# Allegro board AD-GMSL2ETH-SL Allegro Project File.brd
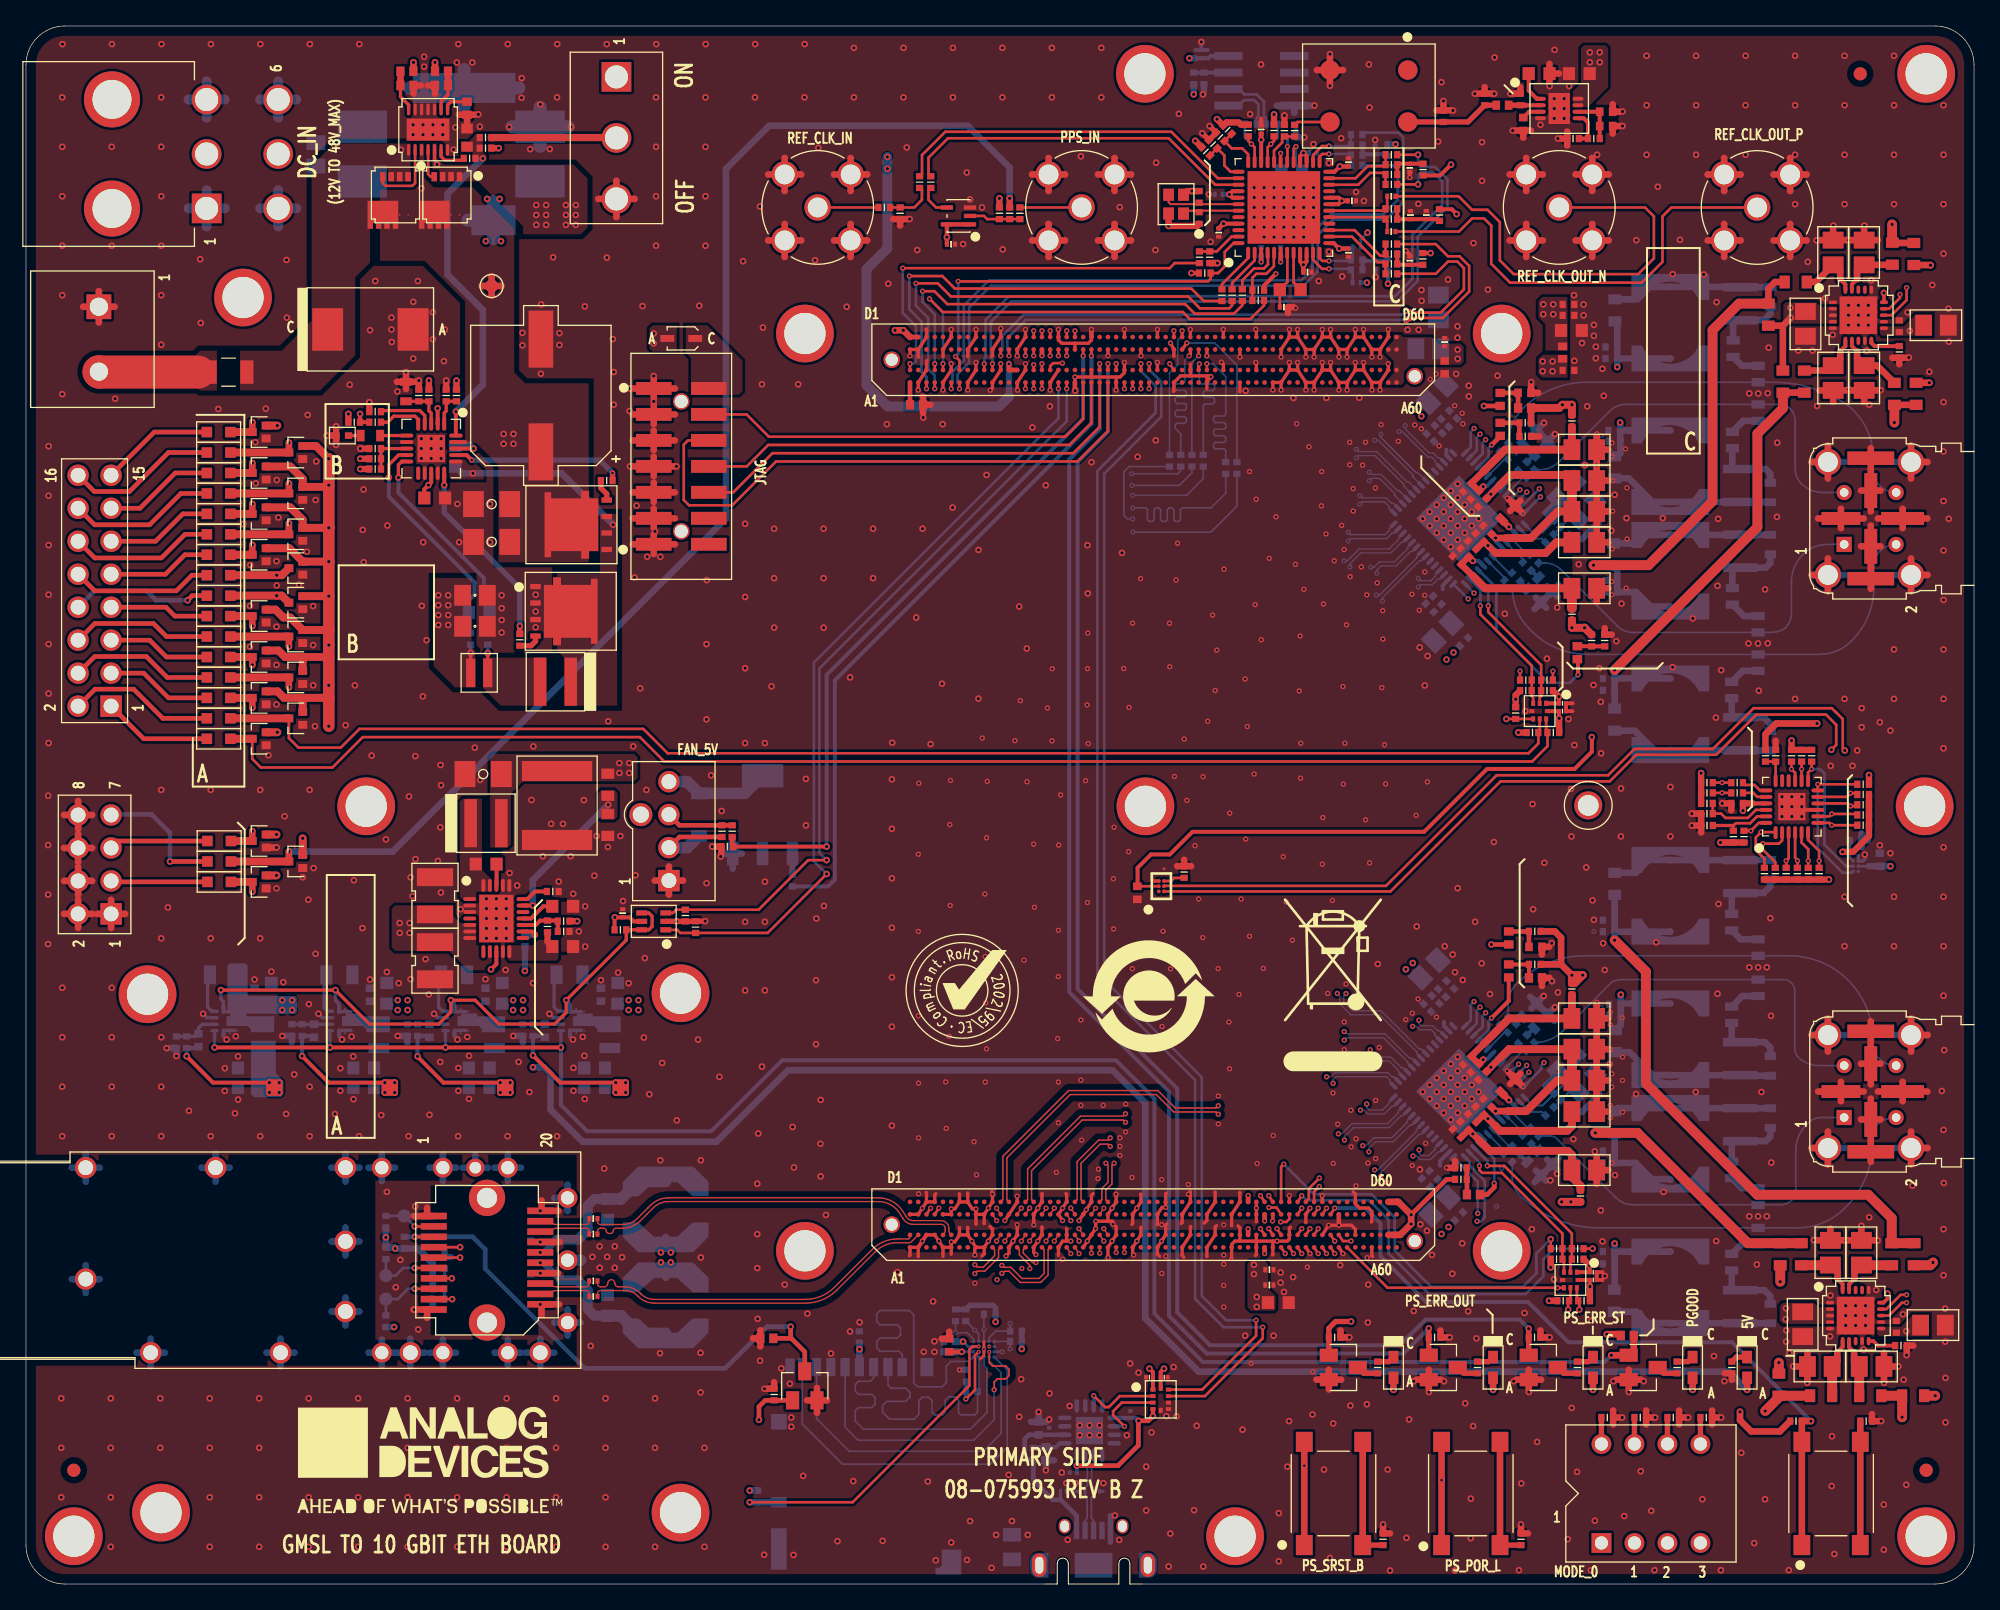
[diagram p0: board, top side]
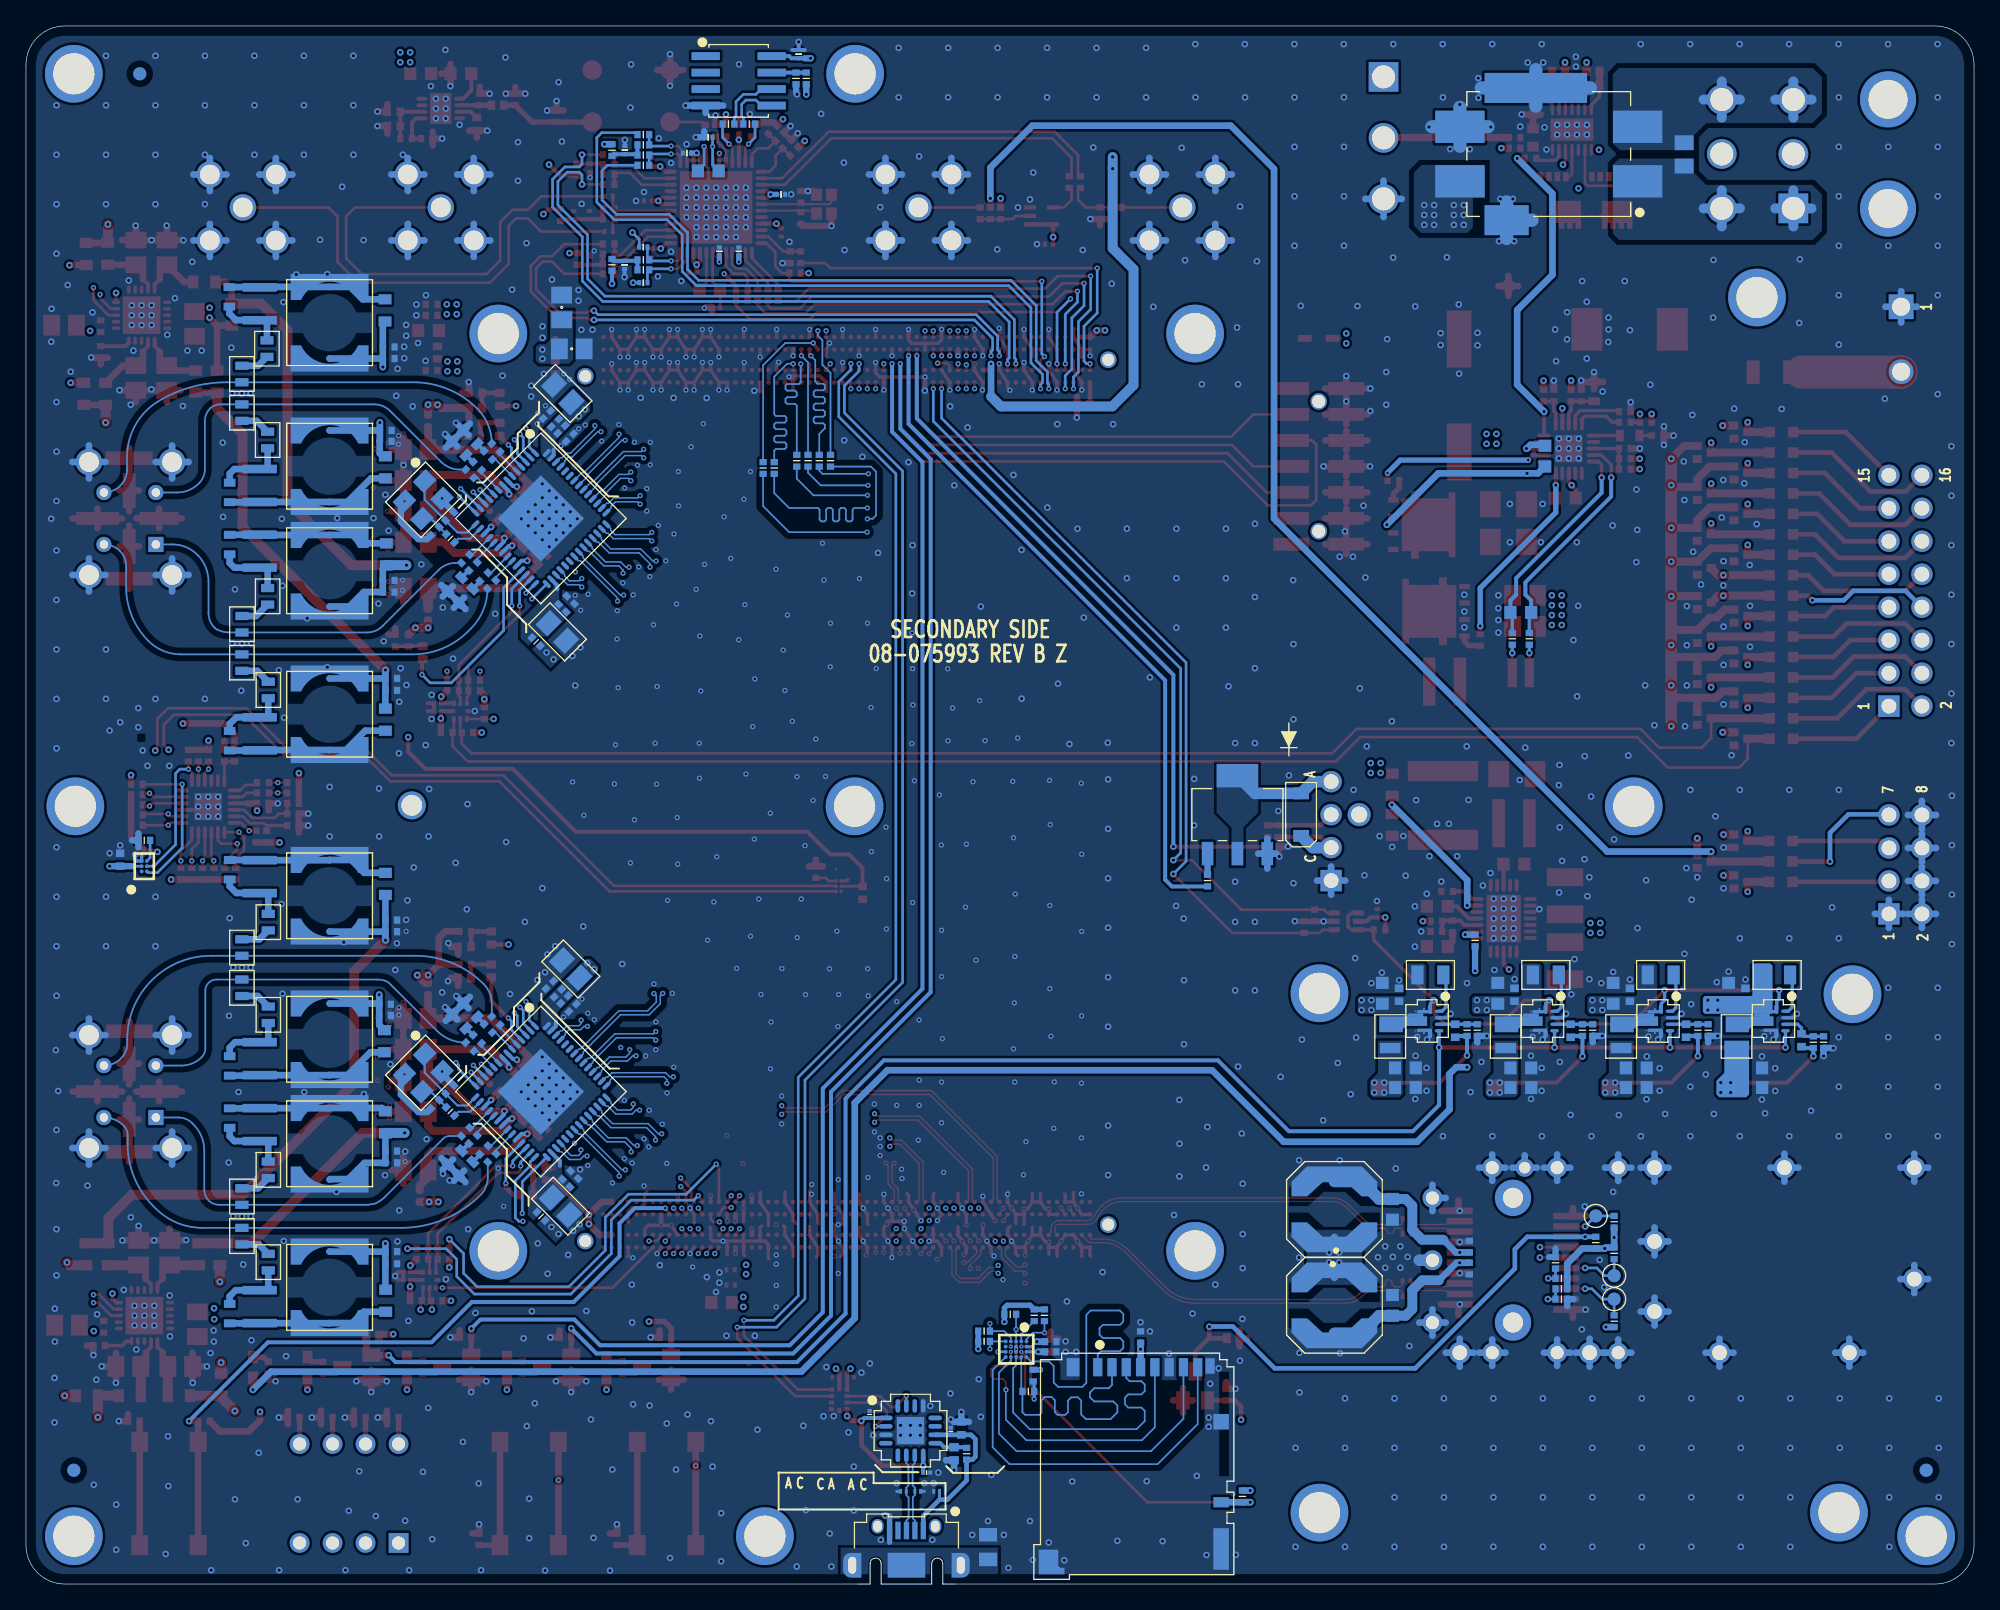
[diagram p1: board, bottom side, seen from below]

Outline 150 x 120 mm; copper layers: TOP, L2_GND, L3_SIG, L4_GND, L5_PWR, L6_PWR, L7_GND, L8_SIG, L9_GND, BOTTOM. Coordinates in mm from the lower left corner of the outline.
Outline path: 0,117 0,3 arc(0.88,0.88) 3,0 79.4,0 79.4,1.58 arc(79.83,2) 80.25,1.58 80.25,0 84.15,0 84.15,1.58 arc(84.58,2) 85,1.58 85,0 147,0 arc(149.12,0.88) 150,3 150,117 arc(149.12,119.12) 147,120 3,120 arc(0.88,119.12) 0,117

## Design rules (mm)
constraint set DEFAULT: min track width 0.203
net group DP_USB: nets USB_DEBUG_N USB_DEBUG_P
net group MG_MIPI1_DP1: nets B_DB3N/DF1N/B3C/F1C B_DB3P/DF1P/B3B/F1B
net group MG_MIPI1_DP2: nets B_DB2N/DF0N/B2B/F0B B_DB2P/DF0P/B2A/F0A
net group MG_MIPI1_DP3: nets B_DB1N/DE1N/B1C/E1C B_DB1P/DE1P/B1B/E1B
net group MG_MIPI1_DP4: nets B_CKBN/CKEN/B1A/E1A B_CKBP/CKEP/B0C/E0C
net group MG_MIPI1_DP5: nets B_DB0N/DE0N/B0B/E0B B_DB0P/DE0P/B0A/E0A
net group MG_MIPI1_DP6: nets B_DA3N/DD1N/A3C/D1C B_DA3P/DD1P/A3B/D1B
net group MG_MIPI1_DP7: nets B_CKAN/CKDN/A3A/D1A B_CKAP/CKDP/A2C/D0C
net group MG_MIPI1_DP8: nets B_DA2N/DD0N/A2B/D0B B_DA2P/DD0P/A2A/D0A
net group MG_MIPI1_DP9: nets B_DA1N/DC1N/A1C/C1C B_DA1P/DC1P/A1B/C1B
net group MG_MIPI1_DP10: nets B_DA0N/DC0N/A0B/C0B B_DA0P/DC0P/A0A/C0A
net group MG_MIPI2_DP1: nets A_DB3N/DF1N/B3C/F1C A_DB3P/DF1P/B3B/F1B
net group MG_MIPI2_DP2: nets A_DB2N/DF0N/B2B/F0B A_DB2P/DF0P/B2A/F0A
net group MG_MIPI2_DP3: nets A_DB1N/DE1N/B1C/E1C A_DB1P/DE1P/B1B/E1B
net group MG_MIPI2_DP4: nets A_CKBN/CKEN/B1A/E1A A_CKBP/CKEP/B0C/E0C
net group MG_MIPI2_DP5: nets A_DB0N/DE0N/B0B/E0B A_DB0P/DE0P/B0A/E0A
net group MG_MIPI2_DP6: nets A_DA3N/DD1N/A3C/D1C A_DA3P/DD1P/A3B/D1B
net group MG_MIPI2_DP7: nets A_CKAN/CKDN/A3A/D1A A_CKAP/CKDP/A2C/D0C
net group MG_MIPI2_DP8: nets A_DA2N/DD0N/A2B/D0B A_DA2P/DD0P/A2A/D0A
net group MG_MIPI2_DP9: nets A_DA1N/DC1N/A1C/C1C A_DA1P/DC1P/A1B/C1B
net group MG_MIPI2_DP10: nets A_DA0N/DC0N/A0B/C0B A_DA0P/DC0P/A0A/C0A
net group SFP_DP1_1: nets UNNAMED_11_CAP_I31_N2 UNNAMED_11_CAP_I32_N2
net group SFP_DP2: nets UNNAMED_11_CAP_I29_N2 UNNAMED_11_CAP_I30_N2
net group SFP_RX_MG: nets SFP+_RX_N SFP+_RX_P
net group SFP_TX_MG: nets SFP+_TX_N SFP+_TX_P
net group SD_CARD_MG: nets SDIO_CLK SDIO_CMD SDIO_DAT0 SDIO_DAT1 SDIO_DAT2 SDIO_DAT3
net group SDCARD_0: nets UNNAMED_6_CN240PABCD_I2_N36 UNNAMED_6_CN240PABCD_I2_N37 UNNAMED_6_CN240PABCD_I3_N34 UNNAMED_6_CN240PABCD_I3_N35 UNNAMED_6_CN240PABCD_I3_N36 UNNAMED_6_CN240PABCD_I4_N34
net group SDCARD_1: nets PS_MIO46_501_SDIO_DAT0 PS_MIO47_501_SDIO_DAT1 PS_MIO48_501_SDIO_DAT2 PS_MIO49_501_SDIO_DAT3 PS_MIO50_501_SDIO_CMD PS_MIO51_501_SDIO_CLK

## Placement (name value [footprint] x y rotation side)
C1  22uF  [C0603]  44.78 28.85 270 bottom
C2  0.1uF  [C0402]  38.86 24.29 270 bottom
C3  0.1uF  [C0402]  38.86 25.99 90 bottom
C4  10uF  [C0805H53]  119.99 87.37 0 top
C5  0.1uF  [C0402]  110.97 84.45 225 top
C6  0.01UF  [C0402]  111.56 83.86 225 top
C7  10uF  [C0805H53]  119.99 84.99 0 top
C8  10uF  [C0805H53]  108.66 91.69 45 bottom
C9  0.1uF  [C0402]  112.52 81.2 135 top
C10  27pF  [C0402]  117.37 82.22 135 bottom
C11  0.1uF  [C0402]  108.74 88.32 225 bottom
C12  0.1uF  [C0402]  109.28 90.04 45 bottom
C13  0.01UF  [C0402]  109.87 89.45 45 bottom
C14  0.01UF  [C0402]  108.15 88.91 225 bottom
C15  10uF  [C0805H53]  119.99 82.61 0 top
C16  0.1uF  [C0402]  112.14 83.28 225 top
C17  22pF  [C0402]  118.5 81.09 315 bottom
C18  0.1uF  [C0402]  111.94 80.61 135 top
C19  0.01UF  [C0402]  111.35 80.03 135 top
C20  0.01UF  [C0402]  110.77 79.44 135 top
C21  0.1uF  [C0402]  110.19 78.86 135 top
C22  10uF  [C0805H53]  119.99 76.69 0 top
C23  0.01UF  [C0402]  108.67 75.77 135 bottom
C24  0.1uF  [C0402]  108.09 75.18 135 bottom
C25  10uF  [C0805H53]  109.08 73.33 225 bottom
C26  10uF  [C0805H53]  137.02 97.05 270 top
C27  10uF  [C0805H53]  139.15 102.55 90 top
C28  10uF  [C0805H53]  139.15 92.89 270 top
C29  10uF  [C0805H53]  141.54 92.89 270 top
C30  10uF  [C0805H53]  141.54 102.55 90 top
C31  0.1uF  [C0402]  144.25 96.88 90 top
C32  10uF  [C0805H53]  147.07 96.95 0 top
C33  0.1uF  [C0402]  121.87 68.83 180 bottom
C34  0.1uF  [C0402]  122.07 76.4 180 bottom
C35  0.1uF  [C0402]  122.3 88.85 180 bottom
C36  0.1uF  [C0402]  122.07 95.28 180 bottom
C37  0.01UF  [C0402]  121.87 69.75 180 bottom
C38  0.01UF  [C0402]  122.07 77.29 180 bottom
C39  0.01UF  [C0402]  122.3 88.01 180 bottom
C40  0.01UF  [C0402]  122.07 94.39 180 bottom
C41  0.22UF  [C0402]  114.73 77.56 315 bottom
C42  0.22UF  [C0402]  115.57 78.38 315 bottom
C43  0.22UF  [C0402]  115.24 86.1 45 bottom
C44  0.22UF  [C0402]  114.4 86.94 45 bottom
C45  0.22UF  [C0402]  114.15 76.98 135 bottom
C46  0.22UF  [C0402]  116.15 78.96 135 bottom
C47  0.22UF  [C0402]  115.82 85.51 225 bottom
C48  0.22UF  [C0402]  113.82 87.52 225 bottom
C49  0.1uF  [C0402]  122.35 44.65 180 bottom
C50  0.1uF  [C0402]  121.87 51.13 180 bottom
C51  0.1uF  [C0402]  121.87 24.66 180 bottom
C52  0.1uF  [C0402]  121.87 33.35 180 bottom
C53  0.01UF  [C0402]  122.35 43.79 180 bottom
C54  0.01UF  [C0402]  121.87 50.24 180 bottom
C55  0.01UF  [C0402]  121.87 25.6 180 bottom
C56  0.01UF  [C0402]  121.87 32.44 180 bottom
C57  0.22UF  [C0402]  114.73 33.43 315 bottom
C58  0.22UF  [C0402]  115.57 34.24 315 bottom
C59  0.22UF  [C0402]  115.24 41.96 45 bottom
C60  0.22UF  [C0402]  114.4 42.8 45 bottom
C61  0.22UF  [C0402]  115.82 41.38 225 bottom
C62  0.22UF  [C0402]  113.82 43.38 225 bottom
C63  0.22UF  [C0402]  114.12 32.82 135 bottom
C64  0.22UF  [C0402]  116.15 34.82 135 bottom
C65  10uF  [C0805H53]  119.99 43.56 0 top
C66  0.1uF  [C0402]  110.97 40.31 225 top
C67  0.01UF  [C0402]  111.56 39.73 225 top
C68  10uF  [C0805H53]  119.99 41.19 0 top
C69  0.1uF  [C0402]  112.14 39.14 225 top
C70  10uF  [C0805H53]  108.05 47.37 45 bottom
C71  27pF  [C0402]  117.37 38.09 135 bottom
C72  0.1uF  [C0402]  108.51 44.4 225 bottom
C73  0.1uF  [C0402]  109.06 46.13 45 bottom
C74  0.01UF  [C0402]  107.93 45 225 bottom
C75  0.01UF  [C0402]  109.64 45.53 45 bottom
C76  10uF  [C0805H53]  119.99 38.79 0 top
C77  0.1uF  [C0402]  112.52 37.06 135 top
C78  22pF  [C0402]  118.5 36.95 315 bottom
C79  0.1uF  [C0402]  111.94 36.47 135 top
C80  0.01UF  [C0402]  111.35 35.89 135 top
C81  0.01UF  [C0402]  110.77 35.31 135 top
C82  0.1uF  [C0402]  110.19 34.72 135 top
C83  10uF  [C0805H53]  119.99 31.88 0 top
C84  0.01UF  [C0402]  108.38 31.5 135 bottom
C85  0.1uF  [C0402]  107.8 30.91 135 bottom
C86  10uF  [C0805H53]  108.84 29.11 225 bottom
C87  10uF  [C0805H53]  136.81 20.01 270 top
C88  10uF  [C0805H53]  138.94 25.52 90 top
C89  10uF  [C0805H53]  138.13 16.76 180 top
C90  10uF  [C0805H53]  142.11 16.76 0 top
C91  10uF  [C0805H53]  141.33 25.52 90 top
C92  0.1uF  [C0402]  144.02 19.81 90 top
C93  10uF  [C0805H53]  146.84 19.94 0 top
C94  0.1uF  [C0201]  99.11 110.21 0 bottom
C95  0.1uF  [C0201]  101.83 102.54 270 top
C96  0.22uF  [C0201]  96.86 98.35 0 top
C97  0.1uF  [C0201]  102.09 106.53 0 top
C98  0.1uF  [C0201]  71.23 103.19 0 top
C99  0.1uF  [C0201]  98.68 101.04 0 top
C100  3900pF  [C0603]  97.34 99.7 0 top
C101  0.1uF  [C0201]  91.85 104.09 270 top
C102  0.1uF  [C0201]  101.83 109.5 90 top
C103  1uF  [C0402]  118.77 98.55 0 top
C104  1uF  [C0402]  118.77 97.71 0 top
C105  10uF  [C0603]  119 96.55 0 top
C106  1uF  [C0402]  118.77 93.47 0 top
C107  15pF  [C0402]  90.33 105.21 270 top
C108  15pF  [C0402]  90.33 106.84 270 top
C109  1uF  [C0402]  115.06 114.34 90 top
C110  0.1uF  [C0201]  95.11 102.64 90 bottom
C111  0.1uF  [C0201]  95.11 112.03 90 top
C112  1uF  [C0402]  112.32 114.34 90 top
C113  3900pF  [C0603]  97.46 108.84 180 bottom
C114  0.1uF  [C0201]  118.31 67.83 0 top
C115  0.1uF  [C0201]  118.31 67.23 0 top
C116  0.22uF  [C0201]  97.46 111.43 0 bottom
C117  0.1uF  [C0402]  109.14 113.05 90 top
C118  10uF  [C0603]  116.51 116.33 0 top
C119  0.1uF  [C0201]  90.5 117.83 90 bottom
C120  0.1uF  [C0201]  103.89 110.44 270 bottom
C121  0.1uF  [C0201]  43.69 23.34 180 top
C122  0.1uF  [C0201]  103.91 101.6 90 bottom
C123  0.1uF  [C0201]  120.68 24.02 0 top
C124  0.1uF  [C0201]  120.68 23.42 0 top
C125  0.1uF  [C0201]  43.69 28.14 180 top
C126  0.1uF  [C0201]  43.69 22.15 180 top
C127  0.1uF  [C0201]  102.46 100.23 0 bottom
C128  0.1uF  [C0201]  102.46 102.97 0 bottom
C129  10uF  [C0603]  18.89 45.5 90 bottom
C130  10uF  [C0603]  45.56 45.5 90 bottom
C131  10uF  [C0603]  27.78 45.5 90 bottom
C132  1uF  [C0402]  17.6 45.39 90 bottom
C133  1uF  [C0402]  44.27 45.39 90 bottom
C134  1uF  [C0402]  26.49 45.39 90 bottom
C135  10pF  [C0402]  22.17 42.61 90 bottom
C136  22uF  [C0603]  17.12 38.24 180 bottom
C137  22uF  [C0603]  43.79 39.75 180 bottom
C138  22uF  [C0603]  26.01 39.75 180 bottom
C139  22uF  [C0603]  17.12 39.75 180 bottom
C140  22uF  [C0603]  43.79 38.24 180 bottom
C141  22uF  [C0603]  26.01 38.24 180 bottom
C142  0.1uF  [C0201]  43.69 26.95 180 top
C143  0.1uF  [C0402]  142.75 55.79 90 bottom
C144  0.1uF  [C0402]  85.57 53.24 270 top
C145  10pF  [C0402]  39.95 42.61 90 bottom
C146  10pF  [C0402]  31.06 42.61 90 bottom
C147  10pF  [C0402]  13.28 41.88 90 bottom
C148  0.1uF  [C0201]  106.55 101.92 270 top
C149  0.1uF  [C0201]  105.13 104.17 0 top
C150  0.1uF  [C0201]  105.13 106.88 0 top
C151  0.1uF  [C0201]  106.55 109.07 90 top
C152  10uF  [C0805H53]  119.99 80.23 0 top
C153  0.1uF  [C0402]  115.39 91.74 0 top
C154  10uF  [C0805H53]  119.99 36.39 0 top
C155  0.1uF  [C0402]  116.23 49.07 0 top
C156  1uF  [C0402]  71.09 18.39 90 top
C157  0.1uF  [C0201]  91.86 107.03 180 bottom
C158  0.1uF  [C0201]  96.61 102.64 90 bottom
C159  47uF  [C0805H60]  107.98 95.14 180 bottom
C160  47uF  [C0805H60]  108.76 98.32 90 bottom
C161  1uF  [C0402]  109.24 93.7 270 top
C162  0.1uF  [C0201]  109.24 95.65 90 top
C163  22uF  [C0603]  96.43 21.68 0 top
C164  0.1uF  [C0201]  95.75 24.21 0 top
C165  0.1uF  [C0201]  95.75 23.03 0 top
C222  47UF  [CPLSMSQ406H488]  39.65 91.54 90 top
C223  2.2uF  [C1206H71]  35.85 80.26 180 top
C224  2.2uF  [C1206H71]  35.85 83.17 180 top
C225  1uF  [C0402]  115.29 112.45 270 top
C226  10uF  [C0603]  119.61 116.33 180 top
C227  1000pF  [C0402H22]  24.36 88.45 180 top
C228  2.2uF  [C0603]  31.47 83.64 0 top
C229  0.1UF  [C0603]  33.05 86.87 270 bottom
C230  22NF  [C0603]  34.9 74.83 180 bottom
C231  47uF  [C0805H60]  34.57 73.76 0 top
C232  47uF  [C0805H60]  34.57 76.15 0 top
C233  0.1uF  [C0402]  121.68 113.39 0 top
C234  1uF  [C0402]  121.68 112.29 0 top
C235  0.1uF  [C0402]  131.76 60.12 180 top
C240  1UF  [C0805]  22.33 110.11 90 bottom
C245  4.7UF  [C1210H110]  31.5 53.01 90 top
C246  4.7UF  [C1210H110]  31.5 48.01 270 top
C247  0.1UF  [C0603]  35.43 55.45 0 top
C248  5600pF  [C0603]  41.33 52.2 0 top
C249  2.2uF  [C0603]  41.33 49.1 0 top
C250  10uF  [C0603]  36.67 45.5 90 bottom
C251  22uF  [C1206H71]  35.2 62.38 180 top
C252  47UF  [C2220H98]  40.89 59.96 270 top
C253  4.7uF  [C0402]  72.44 16.05 90 bottom
C254  22uF  [C0603]  44.78 21.46 90 bottom
C255  0.1uF  [C0402#2]  71.09 18.67 180 bottom
C256  0.1uF  [C0402#2]  71.09 17.88 180 bottom
C257  0.1uF  [C0402#2]  64.18 19.02 90 bottom
C258  0.1uF  [C0201]  85.04 13.06 90 bottom
C259  0.1uF  [C0201]  78.79 11.76 90 bottom
C260  2.2uF  [C0402]  77.98 11.99 90 bottom
C261  0.1uF  [C0201]  80.65 8.59 180 bottom
C262  0.1uF  [C0201]  86.51 15.93 180 top
C263  0.1uF  [C0201]  87.65 15.93 0 top
C267  0.1uF  [C0201]  107.82 105.44 270 top
C268  0.1uF  [C0201]  106.6 105.44 270 top
C271  0.1uF  [C0201]  45.95 51.66 90 top
C272  1000pF  [C0603#2]  33.96 111.4 90 top
C273  1uF  [C0402]  35.38 45.39 90 bottom
C274  22uF  [C0603]  34.9 38.24 180 bottom
C275  22uF  [C0603]  34.9 39.75 180 bottom
D1  MMSD4148T1G  [SOD123-2]  51.82 59.26 90 bottom
D2  SESD0201X1UN-0020-09  [D0201]  79.88 7.14 0 bottom
D3  BAT54JFILM  [SOD323-6]  50.46 95.94 180 top
D4  SESD0201X1UN-0020-09  [D0201]  81.33 7.14 180 bottom
D5  SESD0201X1UN-0020-09  [D0201]  82.43 7.14 0 bottom
D6  RB558WMTL  [SOT416]  20.78 55.65 90 top
D7  RB558WMTL  [SOT416]  17.96 71.4 90 top
D8  RB558WMTL  [SOT416]  17.96 74.55 90 top
D9  RB558WMTL  [SOT416]  17.96 79.27 90 top
D10  RB558WMTL  [SOT416]  17.96 82.42 90 top
D11  RB558WMTL  [SOT416]  17.96 85.57 90 top
D12  RB558WMTL  [SOT416]  17.96 88.72 90 top
D13  SMCJ48A  [DO214AB-4]  26.52 96.63 0 top
D14  RB558WMTL  [SOT416]  20.78 72.97 90 top
D15  RB558WMTL  [SOT416]  20.78 75.58 90 top
D16  RB558WMTL  [SOT416]  20.78 78.24 90 top
D17  RB558WMTL  [SOT416]  20.78 80.85 90 top
D18  RB558WMTL  [SOT416]  20.78 84 90 top
D19  RB558WMTL  [SOT416]  20.78 87.15 90 top
D20  RB558WMTL  [SOT416]  17.96 65.1 90 top
D21  RB558WMTL  [SOT416]  20.78 66.67 90 top
D22  RB558WMTL  [SOT416]  17.96 68.25 90 top
D23  RB558WMTL  [SOT416]  17.96 54.08 90 top
D24  RB558WMTL  [SOT416]  20.78 69.82 90 top
D25  RB558WMTL  [SOT416]  17.96 57.23 90 top
DS6  APT1608SURCK  [LED0603]  105.3 16.68 270 top
DS8  APT1608SURCK  [LED0603]  112.97 16.68 270 top
DS9  APT1608SURCK  [LED0603]  120.66 16.68 270 top
DS10  APT1608SURCK  [LED0603]  128.33 16.68 270 top
DS11  APT1608SURCK  [LED0603]  132.53 16.68 270 top
E1  120OHM  [L0402]  118.32 94.84 270 top
E2  120OHM  [L0402]  113.69 113.89 180 top
F1  10A  [F1206H60]  15.6 93.34 0 top
FL1  BNX026H01L  [FLSML476W358H146]  32.74 110.13 0 bottom
J1  142-0701-201  [CNJOHNSON142-0701-201]  81.28 106.02 0 top
J2  142-0701-201  [CNJOHNSON142-0701-201]  60.96 106.02 0 top
J3  142-0701-201  [CNJOHNSON142-0701-201]  133.3 106.02 0 top
J4  142-0701-201  [CNJOHNSON142-0701-201]  118.06 106.02 0 top
L1  22UH  [LSMSQ240H126]  126.62 66.99 270 bottom
L2  22UH  [LSMSQ240H126]  126.62 78.04 90 bottom
L3  22UH  [LSMSQ240H126]  126.62 86.09 270 bottom
L4  22UH  [LSMSQ240H126]  126.62 97.15 90 bottom
L5  6.8UH  [L1210H118]  132 65.48 90 bottom
L6  6.8UH  [L1210H118]  132 79.55 270 bottom
L7  6.8UH  [L1210H118]  132 84.61 90 bottom
L8  6.8UH  [L1210H118]  132 98.6 270 bottom
L9  0.47UH  [L7144]  131.34 68.86 90 bottom
L10  4.7uH  [LSMSQ236H98]  49.25 21.46 270 bottom
L11  4.7uH  [LSMSQ236H98]  49.25 28.85 90 bottom
L12  0.47UH  [L7144]  131.39 76.07 270 bottom
L13  0.47UH  [L7144]  131.39 88.11 90 bottom
L14  0.47UH  [L7144]  131.44 95.15 270 bottom
L15  22UH  [LSMSQ240H126]  126.62 41.96 270 bottom
L16  22UH  [LSMSQ240H126]  126.62 53.01 90 bottom
L17  22UH  [LSMSQ240H126]  126.62 22.85 270 bottom
L18  22UH  [LSMSQ240H126]  126.62 33.91 90 bottom
L19  6.8UH  [L1210H118]  132 40.46 90 bottom
L20  6.8UH  [L1210H118]  132 54.48 270 bottom
L21  6.8UH  [L1210H118]  132 21.36 90 bottom
L22  6.8UH  [L1210H118]  132 35.38 270 bottom
L23  0.47UH  [L7144]  131.34 43.84 90 bottom
L24  0.47UH  [L7144]  131.34 50.98 270 bottom
L25  0.47UH  [L7144]  131.34 24.79 90 bottom
L26  0.47UH  [L7144]  131.34 31.9 270 bottom
L27  0.33UH  [L0806H39]  18.28 42.17 270 bottom
L28  0.33UH  [L0806H39]  44.95 42.17 270 bottom
L29  0.33UH  [L0806H39]  27.17 42.17 270 bottom
L30  0.47UH  [L7144]  133.38 70.97 90 bottom
L31  1.2UH  [LSMSQ157H122]  40.77 69.49 180 top
L32  0.33UH  [L0806H39]  36.06 42.17 270 bottom
L33  6.8uH  [LSMSQ157H122]  35.42 58.6 0 top
L34  0.47UH  [L7144]  133.37 73.92 270 bottom
L35  0.47UH  [L7144]  133.38 90.22 90 bottom
L36  0.47UH  [L7144]  133.38 93.19 270 bottom
L37  0.47UH  [L7144]  133.38 49.02 270 bottom
L38  0.47UH  [L7144]  133.38 26.8 90 bottom
L39  0.47UH  [L7144]  133.38 29.84 270 bottom
L40  0.47UH  [L7144]  133.38 45.92 90 bottom
M4  2007194-1  [MTE2007194-1]  35.5 24.94 270 top
NOREF  -  []  61.8 229.29 0 top
NOREF#2  -  []  -218.17 164.47 0 top
NOREF#3  -  []  -218.22 187.32 0 top
NOREF#4  -  []  3.68 3.68 0 top
NOREF#5  -  [unnamed#2]  50.4 45.5 270 top
NOREF#6  -  []  148.06 119.81 0 top
NOREF#7  -  [unnamed#2]  3.68 3.68 270 top
NOREF#8  -  []  72.82 231.57 0 top
NOREF#9  -  []  150 39.09 0 top
NOREF#10  -  []  -67.21 -246.71 0 top
NOREF#11  -  []  84.66 7.14 0 top
NOREF#12  -  [unnamed#2]  146.32 116.32 270 top
NOREF#13  -  []  3.68 3.68 0 top
NOREF#14  -  []  82.2 0 0 top
NOREF#15  -  [unnamed#2]  113.63 25.66 270 top
NOREF#16  -  [unnamed#2]  50.4 5.5 270 top
NOREF#17  -  []  70.46 199.62 90 top
NOREF#18  -  []  40.84 111.14 270 top
NOREF#19  -  [unnamed#2]  16.71 99.09 270 top
NOREF#20  -  []  61.8 188.73 0 top
NOREF#21  -  []  86.46 45.26 0 top
NOREF#22  -  [unnamed#2]  113.63 96.31 270 top
NOREF#23  -  [unnamed#2]  59.98 96.31 270 top
NOREF#24  -  []  63.18 173.35 270 top
NOREF#25  -  []  78.87 229.26 90 top
NOREF#26  -  [unnamed#2]  86.2 59.9 270 top
NOREF#27  -  [unnamed#2]  3.68 8.76 0 top
NOREF#28  -  []  109.91 56.39 0 top
NOREF#29  -  [unnamed#2]  141.24 116.32 90 top
NOREF#30  -  []  147 0 90 top
NOREF#31  -  []  -299.4 -266.7 0 top
NOREF#32  -  []  95.1 -77.07 0 top
NOREF#33  -  []  150 3 0 top
NOREF#34  -  []  77.85 148.97 0 top
NOREF#35  -  []  0 3 0 top
NOREF#36  -  []  -299.4 -266.7 0 top
NOREF#37  -  []  3 120 0 top
NOREF#38  -  []  82.2 0 0 top
NOREF#39  -  [unnamed#2]  93.1 3.68 270 top
NOREF#40  -  []  -221.93 210.19 0 top
NOREF#41  -  []  150 83.22 0 top
NOREF#42  -  [unnamed#2]  10.4 5.5 270 top
NOREF#43  -  []  552.22 -2.08 0 top
NOREF#44  -  []  72.82 217.4 0 top
NOREF#45  -  []  3 0 0 top
NOREF#46  -  [unnamed#2]  146.32 8.76 0 top
NOREF#47  -  []  30.53 9.53 0 top
NOREF#48  -  []  83.61 197.96 0 top
NOREF#49  -  []  75.18 235.18 90 top
NOREF#50  -  [unnamed#2]  146.2 59.9 270 top
NOREF#51  -  [unnamed#2]  59.98 25.66 270 top
NOREF#52  -  [unnamed#2]  86.16 116.32 270 top
NOREF#53  -  [unnamed#2]  26.2 59.9 270 top
NOREF#54  -  [unnamed#2]  146.32 3.68 270 top
NOREF#55  -  [unnamed#2]  9.36 45.42 0 top
NOREF#56  -  []  0 117 0 top
NOREF#57  -  []  292.86 77.62 0 top
NOREF#58  -  []  72.09 45.72 0 top
NOREF#59  -  [unnamed#2]  3.68 8.76 0 bottom
NOREF#60  -  []  77.32 -78.51 180 bottom
NOREF#61  -  [unnamed#2]  146.32 8.76 0 bottom
NOREF#62  -  [unnamed#2]  141.24 116.32 90 bottom
P1  2304168-9  [CNTE2304168-X]  140 80.07 90 top
P2  2304168-9  [CNTE2304168-X]  140 35.93 90 top
P3  ADM6-60-01.5-L-4-2-A-TR  [CNSMMHDR4X60L1686W197H163]  86.8 94.29 180 top
P4  1888247-1  [CNAMP1888-247]  35.5 24.94 270 top
P5  ADM6-60-01.5-L-4-2-A-TR  [CNSMMHDR4X60L1686W197H163]  86.8 27.68 180 top
P6  47053-1000  [CNTHMHDR1X4L402W230H402]  49.5 54.18 90 top
P7  87832-1420  [CNMOLEX87832-1420]  50.46 86.08 270 top
P8  1935161  [CNPHOENIX1935161]  5.61 98.37 270 top
P9  DM3BT-DSF-PEJS  [CNHRSDM3BT-DSF-PEJS]  64.7 9 180 bottom
P10  47590-0001  [CNMOLEX47590-0001]  82.2 0 90 bottom
P11  39-30-1060  [CNHDRRA2X3H451]  13.91 105.95 90 top
P12  TSW-108-07-G-D  [CNSAMTECTSW-108-08-G-D-ST]  6.55 67.61 90 top
P13  TSW-104-07-G-D  [CNTHMHDR2X4L400W200H330]  6.55 51.61 90 top
Q1  ZXMS6004DGTA  [SOT223_A]  56.72 59.26 180 bottom
Q2  BSS138TA  [SOT23]  59.97 15.27 0 top
Q3  BSS138LT1G  [SOT23]  101.44 16.68 270 top
Q4  FDMC86160  [POWER33H31]  28.45 106.98 180 top
Q5  SQJA84EP-T1_GE3  [POWERPAKSO5]  42.13 74.92 270 top
Q6  BSS138LT1G  [SOT23]  109.13 16.68 270 top
Q7  SQJA84EP-T1_GE3  [POWERPAKSO5]  41.82 81.58 90 top
Q8  FDMC86160  [POWER33H31]  32.41 106.98 180 top
Q12  BSS138LT1G  [SOT23]  116.83 16.68 270 top
Q13  BSS138LT1G  [SOT23]  124.53 16.68 270 top
R1  0  [R0402]  119.04 89.58 270 top
R2  402  [R0603#2]  114.15 82.52 225 top
R3  0  [R0402]  117.32 80.54 225 bottom
R4  0  [R0402]  119.04 74.7 270 top
R5  0  [R0402]  110.72 72.57 225 bottom
R6  49.9  [R0603#2]  116.13 76.12 315 bottom
R7  49.9  [R0603#2]  116.99 76.98 315 bottom
R8  5.1K  [R0603#2]  134.32 64.95 90 bottom
R9  5.1K  [R0603#2]  134.32 80.06 270 bottom
R10  5.1K  [R0603#2]  134.32 84.07 90 bottom
R11  5.1K  [R0603#2]  134.34 99.14 270 bottom
R12  49.9  [R0603#2]  116.65 87.48 45 bottom
R13  49.9  [R0603#2]  115.79 88.34 45 bottom
R14  49.9  [R0603#2]  116.13 31.98 315 bottom
R15  49.9  [R0603#2]  116.99 32.84 315 bottom
R16  5.1K  [R0603#2]  134.32 39.9 90 bottom
R17  5.1K  [R0603#2]  134.32 55.02 270 bottom
R18  5.1K  [R0603#2]  134.32 20.83 90 bottom
R19  5.1K  [R0603#2]  134.32 35.89 270 bottom
R20  49.9  [R0603#2]  116.65 43.34 45 bottom
R21  49.9  [R0603#2]  115.79 44.21 45 bottom
R22  0  [R0402]  119.04 45.83 270 top
R23  402  [R0603#2]  114.15 38.38 225 top
R24  0  [R0402]  117.32 36.4 225 bottom
R25  0  [R0402]  119.69 29.88 270 top
R26  0  [R0402]  110.34 28.32 225 bottom
R27  0  [R0402]  76.53 105.57 270 top
R28  150  [R0402]  66.09 106.02 0 top
R29  10K  [R0402]  74.96 105.57 270 top
R30  49.9  [R0402]  67.31 105.57 270 top
R31  0  [R0402]  68.81 107.98 90 top
R32  0  [R0402]  92.09 99.27 90 top
R33  0  [R0402]  92.87 99.27 90 top
R34  0  [R0402]  93.66 99.27 90 top
R35  0  [R0402]  94.88 98.86 180 top
R36  10K  [R0402]  94.88 99.65 180 top
R37  49.9  [R0402]  69.67 107.98 90 top
R38  4.7K  [R0402]  90.85 110.34 315 top
R39  0  [R0402]  91.41 110.9 135 top
R40  4.7K  [R0402]  92.52 112.01 315 top
R41  10K  [R0402]  114.71 67.08 270 top
R42  4.7K  [R0402]  94.12 111.95 270 top
R43  470  [R0402]  96.9 111.94 270 top
R44  0  [R0402]  97.69 111.94 90 top
R45  4.7K  [R0402]  96.1 111.95 270 top
R46  49.9  [R0402]  102.46 110.06 0 bottom
R47  49.9  [R0402]  102.46 110.85 180 bottom
R48  4.7K  [R0402]  89.92 115.96 90 bottom
R49  4.7K  [R0402]  90.7 115.96 270 bottom
R50  47.5K  [R0402]  51.56 50.6 90 top
R51  47.5K  [R0402]  50.77 51.49 270 top
R52  49.9  [R0402]  102.46 101.22 0 bottom
R53  49.9  [R0402]  102.46 101.98 180 bottom
R54  0  [R0402]  95.91 112.45 0 bottom
R55  49.9  [R0402]  104.88 110.44 90 bottom
R56  4.7K  [R0201]  117.61 65.58 180 top
R57  49.9  [R0402]  104.88 101.6 270 bottom
R58  0  [R0402]  94.31 112.45 180 bottom
R59  4.7K  [R0402]  31.78 23.54 0 bottom
R60  4.7K  [R0402]  32.23 24.74 90 bottom
R61  4.7K  [R0402]  31.78 22.73 0 bottom
R62  4.7K  [R0402]  31.78 21.94 180 bottom
R63  499  [R0402]  104.5 3.45 90 top
R64  0  [R0402]  129.38 12.83 0 top
R65  0  [R0402]  126.84 12.83 0 top
R66  0  [R0402]  124.3 12.83 0 top
R67  499  [R0402]  115.11 3.45 90 top
R68  0  [R0402]  121.76 12.83 0 top
R69  4.7K  [R0201]  119.97 21.82 180 top
R70  80.6K  [R0402]  116.18 47.73 180 top
R71  10  [R0805H20]  15.16 46.91 180 bottom
R72  10  [R0805H20]  41.86 46.91 180 bottom
R73  10  [R0805H20]  24.13 46.91 180 bottom
R74  102K  [R0402]  12.37 41.73 90 bottom
R75  18.2K  [R0402]  11.58 41.73 270 bottom
R76  47.5K  [R0402]  39.04 42.66 90 bottom
R77  18.2K  [R0402]  38.25 42.66 270 bottom
R78  140K  [R0402]  21.26 42.66 90 bottom
R79  100K  [R0402]  20.47 42.66 270 bottom
R80  4.7K  [R0402]  137.5 63.79 270 top
R81  4.7K  [R0402]  135.95 63.79 270 top
R82  4.7K  [R0402]  141.46 61.59 180 top
R83  4.7K  [R0402]  136.72 63.79 270 top
R84  10K  [R0402]  140.89 57.28 0 bottom
R85  20K  [R0402]  89.18 54.84 90 top
R86  49.9  [R0402]  105.14 101.68 0 top
R87  49.9  [R0402]  105.14 102.44 180 top
R88  49.9  [R0402]  107.55 102.06 90 top
R89  0  [R0402]  108.84 105.44 90 top
R90  0  [R0402]  105.14 100.91 0 top
R91  0  [R0402]  105.14 103.2 0 top
R92  49.9  [R0402]  105.14 108.56 0 top
R93  0  [R0402]  31.03 91.54 270 top
R94  0  [R0402]  30.25 91.54 90 top
R95  100K  [R0603#2]  29.26 91.84 90 top
R96  0  [R0402]  33.15 91.54 270 top
R97  0  [R0402]  32.36 91.54 90 top
R98  1K  [R0402]  59.02 54.18 90 bottom
R99  12K  [R0402]  26.89 90.3 180 top
R100  10K  [R0402]  25.27 89.48 0 top
R101  10K  [R0402]  53.59 57.99 90 top
R102  100K  [R0603#2]  26.52 88.45 180 top
R103  5.6K  [R0402]  54.38 57.99 270 top
R104  10K  [R0402]  54 56.79 180 top
R105  0  [R0402]  120.73 111.33 0 top
R106  4.02  [R0402]  44.72 84.99 180 top
R107  1  [R0402]  38.02 72.72 270 top
R108  0  [R0402]  35.56 72.8 90 bottom
R109  0.008  [R0508]  34.9 70.18 180 top
R110  0  [R0402]  26.89 86.66 180 top
R111  0  [R0402]  34.24 72.8 90 bottom
R112  0  [R0402]  26.89 85.88 0 top
R113  4.7K  [R0402]  133.94 63.79 270 top
R114  4.7K  [R0402]  134.72 63.79 90 top
R115  10K  [R0402]  116.18 50.27 180 top
R116  4.7K  [R0402]  129.44 58.42 180 top
R117  4.7K  [R0402]  129.43 60.12 0 top
R118  4.7K  [R0402]  129.43 59.34 180 top
R119  2.7K  [R0402]  129.43 61.72 0 top
R120  2.7K  [R0402]  129.43 60.94 0 top
R121  4.7K  [R0402]  132.29 57.56 90 top
R122  0  [R0402]  131.76 61.72 0 top
R123  0  [R0402]  131.76 60.94 0 top
R124  4.7K  [R0201]  116 65.58 0 top
R125  0  [R0402]  117.12 69.62 0 top
R126  0  [R0402]  115.49 69.62 180 top
R127  4.7K  [R0402]  138.07 54.71 90 top
R128  49.9  [R0402]  105.14 109.32 180 top
R129  4.7K  [R0402]  141.46 59.23 180 top
R130  10K  [R0402]  72.36 20.7 270 bottom
R131  10K  [R0402]  71.58 20.7 270 bottom
R132  10K  [R0402]  76.23 18.68 180 bottom
R133  4.7K  [R0402]  137.24 54.71 90 top
R134  4.7K  [R0402]  141.46 58.45 180 top
R135  10K  [R0402]  72.82 14.83 0 bottom
R136  4.7K  [R0402]  56.34 6.75 270 bottom
R137  4.7K  [R0402]  141.46 60.81 180 top
R138  4.7K  [R0402]  141.46 60.02 180 top
R139  49.9  [R0402]  107.58 108.94 270 top
R140  0  [R0402]  102.46 111.63 0 bottom
R141  100  [R0402]  35.38 111.4 0 top
R142  4.7K  [R0402]  131.47 57.56 90 top
R143  0  [R0402]  105.14 107.8 0 top
R144  0  [R0402]  105.14 110.08 0 top
R145  0  [R0402]  113.51 88.93 90 top
R146  4.7K  [R0402]  29.13 26.29 90 bottom
R147  4.7K  [R0402]  27.71 27.9 90 bottom
R148  4.7K  [R0402]  27.71 20.24 90 bottom
R149  10K  [R0402]  57.61 14.6 90 top
R150  4.7K  [R0402]  27.71 25.48 270 bottom
R151  0  [R0402]  119.46 71.73 90 top
R152  1MEG  [R0402]  100.77 19 0 top
R153  330  [R0402]  104.08 16.68 270 top
R154  49.9  [R0402]  113.51 91.24 90 top
R155  4.7K  [R0201]  118.36 21.82 0 top
R156  0  [R0402]  114.17 47.22 90 top
R157  49.9K  [R0402]  144.25 94.89 270 top
R158  4.7K  [R0402]  117.86 25.02 0 top
R159  33  [R0402]  92.38 85.96 90 bottom
R160  33  [R0402]  90.65 86.52 90 bottom
R161  33  [R0402]  88.92 86.52 90 bottom
R162  33  [R0402]  93.24 85.96 90 bottom
R163  33  [R0402]  89.78 86.52 90 bottom
R164  33  [R0402]  88.05 86.52 90 bottom
R165  49.9K  [R0402]  144.37 18.36 0 top
R166  4.7K  [R0402]  115.49 68.81 0 top
R167  4.7K  [R0402]  117.12 68.81 180 top
R168  10K  [R0402]  115.44 89.43 180 top
R169  10K  [R0402]  115.44 88.39 0 top
R170  10K  [R0402]  120.55 72.67 270 top
R171  10K  [R0402]  121.56 72.67 90 top
R172  10K  [R0402]  115.39 90.58 180 top
R173  0  [R0402]  119.48 25.83 0 top
R174  0  [R0402]  117.86 25.83 180 top
R175  4.7K  [R0402]  119.48 25.02 180 top
R176  20.5K  [R0402]  116.23 46.69 0 top
R177  10K  [R0402]  110.49 31.17 0 top
R178  10K  [R0402]  110.49 32.05 180 top
R179  4.7K  [R0402]  134.7 54.71 90 top
R180  1K  [R0805]  75.92 2.84 90 bottom
R181  4.7K  [R0402]  77.57 10.03 90 bottom
R182  8.2K  [R0402]  78.54 10.03 270 bottom
R183  4.7K  [R0402]  133.86 54.71 90 top
R184  4.7K  [R0402]  136.4 54.71 90 top
R185  0  [R0402]  75.74 105.57 270 top
R186  0  [R0402]  111.46 30 180 top
R187  49.9  [R0402]  114.17 49.76 90 top
R188  0  [R0402]  90.36 102.19 90 top
R189  0  [R0603]  136.93 92.61 270 top
R190  49.9  [R0402]  91.15 102.19 270 top
R191  10K  [R0402]  90.77 100.97 0 top
R192  0  [R0603]  136.27 100.28 180 top
R193  0  [R0603]  143.87 91.67 270 top
R194  0  [R0603]  143.71 102.46 90 top
R195  0  [R0603]  135.28 92.61 270 top
R196  0  [R0603]  134.16 97.76 90 top
R197  0  [R0603]  145.54 91.67 270 top
R198  0  [R0603]  145.36 102.44 90 top
R199  499  [R0402]  108.47 19 0 top
R200  330  [R0402]  111.77 16.68 270 top
R201  499  [R0402]  116.16 19 0 top
R202  330  [R0402]  119.46 16.68 270 top
R203  4.7K  [R0402]  135.53 54.71 90 top
R204  0  [R0402]  91.96 111.45 135 top
R205  330  [R0402]  127.14 16.68 270 top
R206  510  [R0402]  131.35 16.68 270 top
R207  49.9  [R0402]  105.13 105.13 180 top
R208  49.9  [R0402]  105.13 105.92 180 top
R209  5.1K  [R0603]  122.33 66.57 270 bottom
R210  5.1K  [R0603]  122.25 79.3 90 bottom
R211  10K  [R0402]  35.38 110.59 180 top
R212  5.1K  [R0603]  122.33 86 270 bottom
R213  5.1K  [R0603]  122.35 98.09 90 bottom
R214  0  [R0603]  142.01 14.5 0 top
R215  0  [R0603]  143.66 25.4 90 top
R216  0  [R0603]  138.23 14.5 180 top
R217  0  [R0402]  102.46 109.27 0 bottom
R218  4.7K  [R0402]  136.29 12.55 0 top
R219  499  [R0402]  141.69 12.55 0 top
R220  10K  [R0402]  45.77 50.39 0 top
R221  100K  [R0402]  29.34 116.51 180 top
R222  15K  [R0402]  29.34 115.42 0 top
R223  100K  [R0402]  32 116.51 0 top
R224  15K  [R0402]  32 115.42 180 top
R225  100K  [R0402]  33.96 113.67 270 top
R226  100  [R0402]  34.16 109.8 0 top
R227  TBD0402  [R0402]  119.13 111.33 180 top
R228  10  [R0805H20]  32.97 46.91 180 bottom
R229  120K  [R0402]  30.15 42.66 90 bottom
R230  18.2K  [R0402]  29.36 42.66 270 bottom
R231  0  [R0603]  136.7 25.4 90 top
R232  0  [R0603]  145.39 25.4 90 top
R233  0  [R0603]  134.97 15.35 270 top
R234  0  [R0603]  135.08 25.4 90 top
R235  0  [R0603]  145.31 14.5 180 top
R236  5.1K  [R0603]  122.4 41.81 270 bottom
R237  0  [R0402]  26.89 87.45 180 top
R238  8.06K  [R0402]  40.56 53.34 0 top
R239  0  [R0402]  40.16 50.65 270 top
R240  0  [R0402]  41.4 51.05 0 top
R241  0  [R0402]  41.4 50.27 0 top
R242  82K  [R0603]  44.81 61.56 270 top
R243  9.1K  [R0603]  44.81 58.47 270 top
R244  5.1K  [R0603]  122.33 53.92 90 bottom
R245  5.1K  [R0603]  122.3 21.82 270 bottom
R246  5.1K  [R0603]  122.33 35.56 90 bottom
R247  0  [R0402]  68.57 90.82 0 top
R248  10K  [R0402]  123.3 19.14 0 top
R249  0  [R0402]  26.89 89.48 0 top
R250  0  [R0402]  38.42 49.57 90 bottom
R251  0  [R0402]  57.05 18.92 180 top
R332  10K  [R0402]  76.23 19.48 180 bottom
R333  10K  [R0402]  74.21 20.78 180 bottom
RT1  220  [R0603H35]  14.83 65.1 0 top
RT2  220  [R0603H35]  14.83 68.25 0 top
RT3  220  [R0603H35]  14.83 71.4 0 top
RT4  220  [R0603H35]  14.83 74.55 0 top
RT5  220  [R0603H35]  14.83 79.27 0 top
RT6  220  [R0603H35]  14.83 82.42 0 top
RT7  220  [R0603H35]  14.83 85.57 0 top
RT8  220  [R0603H35]  14.83 88.72 0 top
RT9  220  [R0603H35]  14.83 66.67 0 top
RT10  220  [R0603H35]  14.83 69.82 0 top
RT11  220  [R0603H35]  14.83 72.97 0 top
RT12  220  [R0603H35]  14.83 76.12 0 top
RT13  220  [R0603H35]  14.83 77.7 0 top
RT14  220  [R0603H35]  14.83 80.85 0 top
RT15  220  [R0603H35]  14.83 84 0 top
RT16  220  [R0603H35]  14.83 87.15 0 top
RT17  220  [R0603H35]  14.88 54.08 180 top
RT18  220  [R0603H35]  14.88 57.23 180 top
RT19  220  [R0603H35]  14.88 55.65 180 top
S1  PTS645SK43SMTR92LFS  [SWSMSQ236H169]  100.68 6.97 0 top
S2  CTS206-4  [SWDIP8H335]  121.31 3.16 0 top
S3  PTS645SK43SMTR92LFS  [SWSMSQ236H169]  138.99 6.97 0 top
S6  PTS645SK43SMTR92LFS  [SWSMSQ236H169]  111.25 6.97 0 top
S12  1101M2S3CQE2  [SWTHL500W260H511]  45.47 116.08 270 top
TP1  TESTPAD  [TPSMC40]  29.13 28.35 180 bottom
TP2  TESTPAD  [TPSMC40]  27.71 21.94 180 bottom
TP3  TESTPAD  [TPSMC40]  27.71 23.75 180 bottom
TP5  TESTPAD  [TPSMC40]  35.85 99.97 0 top
TP6  RED  [CNLOOPTP]  120.29 59.97 0 top
U1  MAX96724GTN/VY+  [QFN56_8X8_PAD4_7X4_7H0_8]  110.35 82.07 315 bottom
U2  MAX96724GTN/VY+  [QFN56_8X8_PAD4_7X4_7H0_8]  110.35 37.93 315 bottom
U3  AD9545BCPZ  [QFN48_7X7_PAD5_6X5_6]  96.86 106.02 0 top
U4  LTC3303ARUCM#TRPBF  [QFN12_2X2_05-08-7072]  15.44 43.36 270 bottom
U5  LTC3303ARUCM#TRPBF  [QFN12_2X2_05-08-7072]  42.11 43.36 270 bottom
U6  LTC3303ARUCM#TRPBF  [QFN12_2X2_05-08-7072]  24.33 43.36 270 bottom
U7  MAX31827ANTABRPF+  [WLCSP6H24]  140.89 55.29 180 bottom
U8  MAX31827ANTABRPF+  [WLCSP6H24]  87.43 53.75 0 top
U10  MAX25206ATPA/VY+  [QFN20_4X4_PAD2_1X2_1]  31.2 87.45 180 top
U12  MAX20087ATPA/VY+  [QFN20_4X4_PAD2_9X2_9]  141.1 97.72 270 top
U13  MAX20087ATPA/VY+  [QFN20_4X4_PAD2_9X2_9]  140.88 20.68 270 top
U14  74LVC1G126GW  [SOT353]  71.8 105.37 90 top
U15  24AA16-I/SN  [SO8]  95.12 115.77 270 bottom
U17  ADM7154ACPZ-3.3  [DFN8_3X3_PAD2_38X1_64]  118.06 113.64 270 top
U18  LTC3303ARUCM#TRPBF  [QFN12_2X2_05-08-7072]  33.22 43.36 270 bottom
U19  TCA9548ARGER  [QFN24_4X4_PAD2_1X2_1]  135.97 59.87 0 top
U20  PCA9509GM,125  [QFN8_1_6X1_6H20]  116.56 67.23 180 top
U21  MAX17573ATG+  [QFN24_5X4_PAD3_65X2_65]  36.22 51.26 270 top
U22  NVT4857UKAZ  [WLCSP20-2]  73.76 18.08 0 bottom
U23  FT230XQ-R  [QFN16_4X4_PAD2_1X2_1]  81.89 11.82 270 bottom
U24  FXL2TD245L10X  [QFN10_2_1X1_6]  87.38 14.22 270 top
U25  PCA9509GM,125  [QFN8_1_6X1_6H20]  118.92 23.42 180 top
U26  SN74LVC2G07DCKR  [SC70-6H43]  48.34 51.04 90 top
U27  LTC4355IDE#PBF  [DFN14_4X3_PAD3_3X1_7_05-08-1708]  30.96 112.01 0 top
Y1  25MEGHZ  [YSML126W98H31]  119.41 83.51 315 bottom
Y2  25MEGHZ  [YSML126W98H31]  119.41 39.37 315 bottom
Y3  52MEGHZ  [YSML79W63H20]  88.56 106.28 90 top
Y4  50MEGHZ  [YSML382W295H169]  103.4 114.6 180 top

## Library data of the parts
C1 C136-C141 C163 C254 C274 C275 = CAP: User Part Number: UPN; Tolerance: 20; alternate symbols: (C0603); part number: CAP_SM-22UF,6.3V,20,E021512,C0603; tolerance: 20
C2 C3 C117 C235 = CAP: User Part Number: UPN; Tolerance: 10; alternate symbols: (C0402L); part number: CAP_SM-0.1UF,16V,10,E018707,C0402; tolerance: 10
C4 C7 C8 C15 C22 C25-C30 C32 C65 C68 C70 C76 C83 C86-C91 C93 C152 C154 = CAP: Tolerance: 20; User Part Number: UPN; alternate symbols: (C0805H53); part number: CAP_SM-10UF,16V,20,E025707,C0805H53; tolerance: 20
C5 C9 C11 C12 C16 C18 C21 C24 C31 C33-C36 C49-C52 C66 C69 C72 C73 C77 C79 C82 C85 C92 C153 C155 = CAP: User Part Number: UPN; Tolerance: 10; alternate symbols: (C0402L); part number: CAP_SM-0.1UF,25V,10,E025798,C0402; tolerance: 10
C6 C13 C14 C19 C20 C23 C37-C40 C53-C56 C67 C74 C75 C80 C81 C84 = CAP: User Part Number: UPN; Tolerance: 10; alternate symbols: (C0402L); part number: CAP_SM-0.01UF,50V,10,E056990,C0402; tolerance: 10
C10 C71 = CAP: User Part Number: UPN; Tolerance: 5; alternate symbols: (C0402L); part number: CAP_SM-27PF,50V,5,E033384,C0402; tolerance: 5
C17 C78 = CAP: User Part Number: UPN; Tolerance: 5; alternate symbols: (C0402L); part number: CAP_SM-22PF,50V,5,E000265,C0402; tolerance: 5
C41-C48 C57-C64 = CAP: User Part Number: UPN; Tolerance: 10; alternate symbols: (C0402L); part number: CAP_SM-0.22UF,35V,10,E056754,C0402; tolerance: 10
C94 C95 C97-C99 C101 C102 C110 C111 C119 C120 C122 C127 C128 C148-C151 C157 C158 C267 C268 = CAP: Tolerance: 10; User Part Number: UPN; alternate symbols: (C0201); part number: CAP_SM-0.1UF,25V,10,E022721,C0201; tolerance: 10
C96 C116 = CAP: Tolerance: 20; User Part Number: UPN; alternate symbols: (C0201); part number: CAP_SM-0.22UF,10V,20,E023047,C0201; tolerance: 20
C100 C113 = CAP: User Part Number: UPN; Tolerance: 5; alternate symbols: (C0603); part number: CAP_SM-3900PF,50V,5,E024825,C0603; tolerance: 5
C103 C104 C106 C109 C112 C156 C225 C234 = CAP: User Part Number: UPN; Tolerance: 20; alternate symbols: (C0402L); part number: CAP_SM-1UF,16V,20,E020695,C0402; tolerance: 20
C105 C118 C226 = CAP: User Part Number: UPN; Tolerance: 20; alternate symbols: (C0603); part number: CAP_SM-10UF,10V,20,E018646,C0603; tolerance: 20
C107 C108 = CAP: User Part Number: UPN; Tolerance: 1; alternate symbols: (C0402L); part number: CAP_SM-15PF,50V,1,E020722,C0402; tolerance: 1
C114 C115 C123 C124 C162 C164 C165 C258 C259 C261-C263 C271 = CAP: Tolerance: 10; User Part Number: UPN; alternate symbols: (C0201L); part number: CAP_SM-0.1UF,25V,10,E022721,C0201; tolerance: 10
C121 C125 C126 C142 = CAP: Tolerance: 10; User Part Number: UPN; alternate symbols: (C0201); part number: CAP_SM-0.1UF,6.3V,10,E011567,C0201; tolerance: 10
C129-C131 C250 = CAP: User Part Number: UPN; Tolerance: 10; alternate symbols: (C0603); part number: CAP_SM-10UF,10V,10,E020723,C0603; tolerance: 10
C132-C134 C161 C273 = CAP: User Part Number: UPN; Tolerance: 10; alternate symbols: (C0402); part number: CAP_SM-1UF,6.3V,10,E011561,C0402; tolerance: 10
C135 C145-C147 = CAP: User Part Number: UPN; Tolerance: 5; alternate symbols: (C0402); part number: CAP_SM-10PF,50V,5,E007982,C0402; tolerance: 5
C143 C144 = CAP: User Part Number: UPN; Tolerance: 10; alternate symbols: (C0402L_ALT); part number: CAP_SM-0.1UF,25V,10,E025798,C0402; tolerance: 10; signal model: capacitor20pF
C159 C160 C231 C232 = CAP: Tolerance: 20; User Part Number: UPN; alternate symbols: (C0805H60); part number: CAP_SM-47UF,10V,20,E022064,C0805H60; tolerance: 20
C222 = CAPP: User Part Number: UPN; Tolerance: 20; alternate symbols: (CPLSMSQ406H488); part number: CAPP_SM-47UF,100V,20,E057020,CPLSMSQ406H488; tolerance: 20
C223 C224 = CAP: Tolerance: 10; User Part Number: UPN; alternate symbols: (C1206H71); part number: CAP_SM-2.2UF,100V,10,E035573,C1206H71; tolerance: 10
C227 = CAP: Tolerance: 10; User Part Number: UPN; alternate symbols: (C0402H22); part number: CAP_SM-1000PF,50V,10,E033487,C0402H22; tolerance: 10
C228 C249 = CAP: User Part Number: UPN; Tolerance: 10; alternate symbols: (C0603); part number: CAP_SM-2.2UF,10V,10,E015288,C0603; tolerance: 10
C229 C247 = CAP: User Part Number: UPN; Tolerance: 10; alternate symbols: (C0603); part number: CAP_SM-0.1UF,100V,10,E048494,C0603; tolerance: 10
C230 = CAP: User Part Number: UPN; Tolerance: 5; alternate symbols: (C0603); part number: CAP_SM-22NF,50V,5,E042676,C0603; tolerance: 5
C233 = CAP: User Part Number: UPN; Tolerance: 10; alternate symbols: (C0402); part number: CAP_SM-0.1UF,16V,10,E018707,C0402; tolerance: 10
C240 = CAP: User Part Number: UPN; Tolerance: 10; alternate symbols: (C0805); part number: CAP_SM-1UF,100V,10,E059993,C0805; tolerance: 10
C245 C246 = CAP: Tolerance: 10; User Part Number: UPN; alternate symbols: (C1210H110); part number: CAP_SM-4.7UF,100V,10,E044145,C1210H110; tolerance: 10
C248 = CAP: User Part Number: UPN; Tolerance: 5; alternate symbols: (C0603); part number: CAP_SM-5600PF,50V,5,E012693,C0603; tolerance: 5
C251 = CAP: Tolerance: 20; User Part Number: UPN; alternate symbols: (C1206H71); part number: CAP_SM-22UF,35V,20,E032398,C1206H71; tolerance: 20
C252 = CAP: User Part Number: UPN; Tolerance: 20; alternate symbols: (C2220H98); part number: CAP_SM-47UF,25V,20,E044247,C2220H98; tolerance: 20
C253 = CAP: User Part Number: UPN; Tolerance: 20; alternate symbols: (C0402L); part number: CAP_SM-4.7UF,6.3V,20,E014207,C0402; tolerance: 20
C255-C257 = CAP: Tolerance: 10; User Part Number: UPN; alternate symbols: (C0402L_ALT); part number: CAP_SM-0.1UF,25V,10,E025798,C0402; tolerance: 10; signal model: capacitor20pF
C260 = CAP: User Part Number: UPN; Tolerance: 10; alternate symbols: (C0402); part number: CAP_SM-2.2UF,16V,10,E033903,C0402; tolerance: 10
C272 = CAP: User Part Number: UPN; Tolerance: 5; alternate symbols: (C0603L); part number: CAP_SM-1000PF,100V,5,E012694,C0603; tolerance: 5
D1 = DIO: User Part Number: UPN; Tolerance: N/A; alternate symbols: (SOD123-2); part number: DIO_SM-MMSD4148T1G,100V,N/A,E005349,SOD123-2; tolerance: N/A
D2 D4 D5 = DIO: Tolerance: N/A; User Part Number: UPN; alternate symbols: (D0201); part number: DIO_SM-SESD0201X1UN-0020-09,9V,N/A,E022225,D0201; tolerance: N/A
D3 = DIOSCHOTTKY: Tolerance: N/A; User Part Number: UPN; alternate symbols: (SOD323-6); part number: DIOSCHOTTKY_SM-BAT54JFILM,40V,N/A,E014201,SOD323-6; tolerance: N/A
D6-D12 D14-D25 = DIOSCHOTTKY3P_V9: User Part Number: UPN; Tolerance: N/A; alternate symbols: (SOT416); part number: DIOSCHOTTKY3P_V9_SM-RB558WMTL,30V,N/A,E063585,SOT416; tolerance: N/A
D13 = DIO: User Part Number: UPN; Tolerance: N/A; alternate symbols: (DO214AB-4); part number: DIO_SM-SMCJ48A,N/A,N/A,E019000,DO214AB-4; tolerance: N/A
DS6 DS8-DS11 = DIOLED: Tolerance: N/A; User Part Number: UPN; alternate symbols: (LED0603); part number: DIOLED_SM-APT1608SURCK,N/A,N/A,E021036,LED0603; tolerance: N/A
E1 E2 = FERRITE: User Part Number: UPN; Tolerance: 25; alternate symbols: (L0402); part number: FERRITE_SM-120OHM,25,E010287,L0402; tolerance: 25
F1 = FSFUSE: Tolerance: N/A; User Part Number: UPN; alternate symbols: (F1206H60); part number: FSFUSE_SM-10A,63VDC/32VAC,E041286,F1206H60; tolerance: N/A
FL1 = FLBNX01: User Part Number: UPN; Tolerance: N/A; alternate symbols: (FLSML476W358H146); part number: FLBNX01_SM-BNX026H01L,E050260,FLSML476W358H146; tolerance: N/A
J1-J4 = CNBNC5P: Tolerance: N/A; User Part Number: UPN; alternate symbols: (CNJOHNSON142-0701-201); part number: CNBNC5P_TH-142-0701-201,E000916,CNJOHNSON142-0701-201; tolerance: N/A
L1-L4 L15-L18 = IND: User Part Number: UPN; Tolerance: 20; alternate symbols: (LSMSQ240H126); part number: IND_SM-22UH,20,E062668,LSMSQ240H126; tolerance: 20
L5-L8 L19-L22 = CHOKE2P: User Part Number: UPN; Tolerance: 20; alternate symbols: (L1210H118); part number: CHOKE2P_SM-6.8UH,20,E062669,L1210H118; tolerance: 20
L9 L12-L14 L23-L26 L30 L34-L40 = IND: Tolerance: 20; User Part Number: UPN; alternate symbols: (L7144); part number: IND_SM-0.47UH,20,E025526,L7144; tolerance: 20
L10 L11 = IND: Tolerance: 20; User Part Number: UPN; alternate symbols: (LSMSQ236H98); part number: IND_SM-4.7UH,20,E010081,LSMSQ236H98; tolerance: 20
L27-L29 L32 = IND: Tolerance: 20; User Part Number: UPN; alternate symbols: (L0806H39); part number: IND_SM-0.33UH,20,E048282,L0806H39; tolerance: 20
L31 = IND: User Part Number: UPN; Tolerance: 20; alternate symbols: (LSMSQ157H122); part number: IND_SM-1.2UH,20,E030942,LSMSQ157H122; tolerance: 20
L33 = IND: User Part Number: UPN; Tolerance: 20; alternate symbols: (LSMSQ157H122); part number: IND_SM-6.8UH,20,E017909,LSMSQ157H122; tolerance: 20
M4 = MOD_2007194_1: User Part Number: UPN; Tolerance: N/A; alternate symbols: (MTE2007194-1); part number: MOD_2007194_1_TH-2007194-1,E032195,MTE2007194-1; tolerance: N/A
P1 P2 = CN4P_10GND: User Part Number: UPN; Tolerance: N/A; alternate symbols: (CNTE2304168-X); part number: CN4P_10GND_TH-2304168-9,E061991,CNTE2304168-X; tolerance: N/A
P3 P5 = CN240P_ABCD: User Part Number: UPN; Tolerance: N/A; alternate symbols: (CNSMMHDR4X60L1686W197H163); part number: CN240P_ABCD_SM-ADM6-60-01.5-L-4-2-A-TR,E059430,CNSMMHDR4X60L1686W197H163; tolerance: N/A
P4 = CN20P: Tolerance: N/A; User Part Number: UPN; alternate symbols: (CNAMP1888-247); part number: CN20P_SM-1888247-1,E007079,CNAMP1888-247; tolerance: N/A
P6 = CN4P: Tolerance: N/A; User Part Number: UPN; alternate symbols: (CNTHMHDR1X4L402W230H402); part number: CN4P_TH-47053-1000,E033301,CNTHMHDR1X4L402W230H402; tolerance: N/A
P7 = CN14P: Tolerance: N/A; User Part Number: UPN; alternate symbols: (CNMOLEX87832-1420); part number: CN14P_SM-87832-1420,E005962,CNMOLEX87832-1420; tolerance: N/A
P8 = CN2P: User Part Number: UPN; Tolerance: N/A; alternate symbols: (CNPHOENIX1935161); part number: CN2P_TH-1935161,E035697,CNPHOENIX1935161; tolerance: N/A
P9 = CN10P_4PSHLD_V3: User Part Number: UPN; Tolerance: N/A; alternate symbols: (CNHRSDM3BT-DSF-PEJS); part number: CN10P_4PSHLD_V3_SM-DM3BT-DSF-PEJS,E028449,CNHRSDM3BT-DSF-PEJS; tolerance: N/A
P10 = CN5P_3SHLD: User Part Number: UPN; Tolerance: N/A; alternate symbols: (CNMOLEX47590-0001); part number: CN5P_3SHLD_SM-47590-0001,E015753,CNMOLEX47590-0001; tolerance: N/A
P11 = CN6P: User Part Number: UPN; Tolerance: N/A; alternate symbols: (CNHDRRA2X3H451); part number: CN6P_TH-39-30-1060,E016920,CNHDRRA2X3H451; tolerance: N/A
P12 = CN16P_ODD_EVEN: Tolerance: N/A; User Part Number: UPN; alternate symbols: (CNSAMTECTSW-108-08-G-D-ST); part number: CN16P_ODD_EVEN_TH-TSW-108-07-G-D,E007878,CNSAMTECTSW-108-08-G-D-ST; tolerance: N/A
P13 = CN8P_ODD_EVEN: Tolerance: N/A; User Part Number: UPN; alternate symbols: (CNTHMHDR2X4L400W200H330); part number: CN8P_ODD_EVEN_TH-TSW-104-07-G-D,E042079,CNTHMHDR2X4L400W200H330; tolerance: N/A
Q1 = TRANNMOSFET_4P: User Part Number: UPN; Tolerance: N/A; alternate symbols: (SOT223_A); part number: TRANNMOSFET_4P_SM-ZXMS6004DGTA,E031265,SOT223_A; tolerance: N/A
Q2 = TRANBSS138: User Part Number: UPN; Tolerance: N/A; alternate symbols: (SOT23); part number: TRANBSS138_SM-BSS138-7-F,E004635,SOT23; tolerance: N/A
Q3 Q6 Q12 Q13 = TRANNMOSFET_V8: User Part Number: UPN; Tolerance: N/A; alternate symbols: (SOT23); part number: TRANNMOSFET_V8_SM-BSS138LT1G,E018770,SOT23; tolerance: N/A
Q4 Q8 = TRANNMOSFET_V15: Tolerance: N/A; User Part Number: UPN; alternate symbols: (POWER33H31); part number: TRANNMOSFET_V15_SM-FDMC86160,E054709,POWER33H31; tolerance: N/A
Q5 Q7 = TRANNMOSFET_V13: User Part Number: UPN; Tolerance: N/A; alternate symbols: (POWERPAKSO5); part number: TRANNMOSFET_V13_SM-SQJA84EP-T1_GE3,E062225,POWERPAKSO5; tolerance: N/A
R1 R3-R5 R22 R24-R27 R31-R35 R39 R44 R54 R58 R64-R66 R68 R89-R91 R93 R94 R96 R97 R108 R110-R112 R122 R123 R125 R126 R140 R143-R145 R151 R156 R173 R174 R185 R186 R188 R204 R217 R237 R239-R241 R247 R249-R251 = RES: User Part Number: UPN; Tolerance: JUMPER; alternate symbols: (R0402L); part number: RES_SM-0,E003438,1/10W,JUMPER,R0402; tolerance: JUMPER
R2 R23 = RES: User Part Number: UPN; Tolerance: 1; alternate symbols: (R0603L); part number: RES_SM-402,E003686,1/10W,1,R0603; tolerance: 1
R6 R7 R12-R15 R20 R21 = RES: User Part Number: UPN; Tolerance: 1; alternate symbols: (R0603L); part number: RES_SM-49.9,E003673,1/10W,1,R0603; tolerance: 1
R8-R11 R16-R19 R209 R210 R212 R213 R236 R244-R246 = RES: User Part Number: UPN; Tolerance: 1; alternate symbols: (R0603L); part number: RES_SM-5.1K,E030325,1/10W,1,R0603; tolerance: 1
R28 = RES: User Part Number: UPN; Tolerance: 1; alternate symbols: (R0402L); part number: RES_SM-150,E017444,1/10W,1,R0402; tolerance: 1
R29 R36 R41 R84 R101 R104 R115 R130-R132 R135 R149 R168-R172 R177 R178 R191 R211 R220 R248 R332 R333 = RES: User Part Number: UPN; Tolerance: 1; alternate symbols: (R0402L); part number: RES_SM-10K,E003751,1/10W,1,R0402; tolerance: 1
R30 R37 R46 R47 R52 R53 R55 R57 R86-R88 R92 R128 R139 R154 R187 R190 R207 R208 = RES: User Part Number: UPN; Tolerance: 1; alternate symbols: (R0402L); part number: RES_SM-49.9,E003750,1/10W,1,R0402; tolerance: 1
R38 R40 R42 R45 R48 R49 R59-R62 R80-R83 R113 R114 R116-R118 R121 R127 R129 R133 R134 R136-R138 R142 R146-R148 R150 R158 R166 R167 R175 R179 R181 R183 R184 R203 R218 = RES: User Part Number: UPN; Tolerance: 1; alternate symbols: (R0402L); part number: RES_SM-4.7K,E008190,1/10W,1,R0402; tolerance: 1
R43 = RES: User Part Number: UPN; Tolerance: 1; alternate symbols: (R0402L); part number: RES_SM-470,E042472,1/10W,1,R0402; tolerance: 1
R50 R51 R76 = RES: User Part Number: UPN; Tolerance: 0.1; alternate symbols: (R0402L); part number: RES_SM-47.5K,E055991,1/10W,0.1,R0402; tolerance: 0.1
R56 R69 R124 R155 = RES: User Part Number: UPN; Tolerance: 1; alternate symbols: (R0402L); part number: RES_SM-4.7K,E040337,1/20W,1,R0201; tolerance: 1
R63 R67 R199 R201 R219 = RES: User Part Number: UPN; Tolerance: 1; alternate symbols: (R0402L); part number: RES_SM-499,E003758,1/10W,1,R0402; tolerance: 1
R70 = RES: User Part Number: UPN; Tolerance: 1; alternate symbols: (R0402L); part number: RES_SM-80.6K,E006346,1/10W,1,R0402; tolerance: 1
R71-R73 R228 = RES: Tolerance: 0.1; User Part Number: UPN; alternate symbols: (R0805H20); part number: RES_SM-10,E026825,1W,0.1,R0805H20; tolerance: 0.1
R74 = RES: User Part Number: UPN; Tolerance: 1; alternate symbols: (R0402L); part number: RES_SM-102K,E020517,1/10W,1,R0402; tolerance: 1
R75 R77 R230 = RES: User Part Number: UPN; Tolerance: 0.1; alternate symbols: (R0402L); part number: RES_SM-18.2K,E048482,1/16W,0.1,R0402; tolerance: 0.1
R78 = RES: User Part Number: UPN; Tolerance: 0.1; alternate symbols: (R0402L); part number: RES_SM-140K,E060925,1/10W,0.1,R0402; tolerance: 0.1
R79 = RES: User Part Number: UPN; Tolerance: 0.1; alternate symbols: (R0402L); part number: RES_SM-100K,E025813,1/16W,0.1,R0402; tolerance: 0.1
R85 = RES: User Part Number: UPN; Tolerance: 1; alternate symbols: (R0402L); part number: RES_SM-20K,E003791,1/10W,1,R0402; tolerance: 1
R95 R102 = RES: User Part Number: UPN; Tolerance: 1; alternate symbols: (R0603L); part number: RES_SM-100K,E010279,1/10W,1,R0603; tolerance: 1
R98 = RES: User Part Number: UPN; Tolerance: 1; alternate symbols: (R0402L); part number: RES_SM-1K,E003763,1/10W,1,R0402; tolerance: 1
R99 = RES: User Part Number: UPN; Tolerance: 1; alternate symbols: (R0402L); part number: RES_SM-12K,E016845,1/16W,1,R0402; tolerance: 1
R100 = RES: User Part Number: UPN; Tolerance: 1; alternate symbols: (R0402L); part number: RES_SM-10K,E030849,1/16W,1,R0402; tolerance: 1
R103 = RES: User Part Number: UPN; Tolerance: 1; alternate symbols: (R0402L); part number: RES_SM-5.6K,E062972,1/10W,1,R0402; tolerance: 1
R105 = RES: User Part Number: UPN; Tolerance: JUMPER; alternate symbols: (R0402L); part number: RES_SM-0,E025229,1/16W,JUMPER,R0402; tolerance: JUMPER
R106 = RES: User Part Number: UPN; Tolerance: 1; alternate symbols: (R0402L); part number: RES_SM-4.02,E016605,1/16W,1,R0402; tolerance: 1
R107 = RES: User Part Number: UPN; Tolerance: 5; alternate symbols: (R0402L); part number: RES_SM-1,E010031,1/10W,5,R0402; tolerance: 5
R109 = RES: Tolerance: 1; User Part Number: UPN; alternate symbols: (R0508); part number: RES_SM-0.008,E054934,1W,1,R0508; tolerance: 1
R119 R120 = RES: User Part Number: UPN; Tolerance: 1; alternate symbols: (R0402L); part number: RES_SM-2.7K,E007440,1/10W,1,R0402; tolerance: 1
R141 R226 = RES: User Part Number: UPN; Tolerance: 1; alternate symbols: (R0402L); part number: RES_SM-100,E016329,1/10W,1,R0402; tolerance: 1
R152 = RES: User Part Number: UPN; Tolerance: 1; alternate symbols: (R0402L); part number: RES_SM-1MEG,E003749,1/10W,1,R0402; tolerance: 1
R153 R200 R202 R205 = RES: User Part Number: UPN; Tolerance: 5; alternate symbols: (R0402L); part number: RES_SM-330,E003462,1/10W,5,R0402; tolerance: 5
R157 R165 = RES: User Part Number: UPN; Tolerance: 1; alternate symbols: (R0402L); part number: RES_SM-49.9K,E004901,1/10W,1,R0402; tolerance: 1
R159-R164 = RES: User Part Number: UPN; Tolerance: 1; alternate symbols: (R0402L); part number: RES_SM-33,E020519,1/10W,1,R0402; tolerance: 1
R176 = RES: User Part Number: UPN; Tolerance: 1; alternate symbols: (R0402); part number: RES_SM-20.5K,E017563,1/10W,1,R0402; tolerance: 1
R180 = RES: User Part Number: UPN; Tolerance: 1; alternate symbols: (R0805); part number: RES_SM-1K,E023448,1/2W,1,R0805; tolerance: 1
R182 = RES: User Part Number: UPN; Tolerance: 5; alternate symbols: (R0402); part number: RES_SM-8.2K,E007570,1/10W,5,R0402; tolerance: 5
R189 R192-R198 R214-R216 R231-R235 = RES: User Part Number: UPN; Tolerance: JUMPER; alternate symbols: (R0603); part number: RES_SM-0,E006826,1/10W,JUMPER,R0603; tolerance: JUMPER
